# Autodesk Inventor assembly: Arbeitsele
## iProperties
Shininess: 64.0
Length Units: 11269
Angle Units: 11279
Time Units: 11290
Mass Units: 11283
Length Display Precision: 3
Angle Display Precision: 2
Compacted: True
Created: 2003-05
Part Number: Arbeitsele
Document SubType Name: Assembly
Designer: chefe
Density: 0.0
Volumn: 0.0
Area: 0.0
PropertySet Name: Model Information
Control State: 0
Master: False
Checked Out: False
Author: chefe
